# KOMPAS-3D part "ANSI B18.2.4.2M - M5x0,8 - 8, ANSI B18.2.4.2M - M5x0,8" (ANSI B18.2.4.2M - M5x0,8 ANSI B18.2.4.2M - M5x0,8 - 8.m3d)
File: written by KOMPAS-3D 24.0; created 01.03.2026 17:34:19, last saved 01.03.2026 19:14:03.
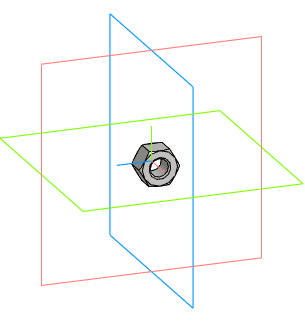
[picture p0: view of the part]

Document properties: Автор: R2D2; Полное имя файла: E:\Работа\Зайцев\GVWR3131M-2W-F-S Задвижка клиновая с выдвижным штоком DN.ru Ду50-200 Ру63\DN50\исходные материалы\ANSI B18.2.4.2M - M5x0,8 ANSI B18.2.4.2M - M5x0,8 - 8.m3d

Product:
- Body: Solid1  | qty 1
    Масса: 0.00167
- Body: Solid1  | qty 1
    Масса: 0.00167
- Part/product: ANSI B18.2.4.2M - M5x0,8 - 8  | designation ANSI B18.2.4.2M - M5x0,8
    Масса: 0.00167
    Комментарий: Типы метрических   шестигранных гаек   2
    additional columns: Сталь, мягкая
- Part/product: ANSI B18.2.4.2M - M5x0,8 - 8  | designation ANSI B18.2.4.2M - M5x0,8-01
    Масса: 0.00167
    Комментарий: Типы метрических   шестигранных гаек   2
    additional columns: Сталь, мягкая

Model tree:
1. Solid1  (labels: Solid1)

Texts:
  ANSI B18.2.4.2M - M5x0,8
  ANSI B18.2.4.2M - M5x0,8-01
